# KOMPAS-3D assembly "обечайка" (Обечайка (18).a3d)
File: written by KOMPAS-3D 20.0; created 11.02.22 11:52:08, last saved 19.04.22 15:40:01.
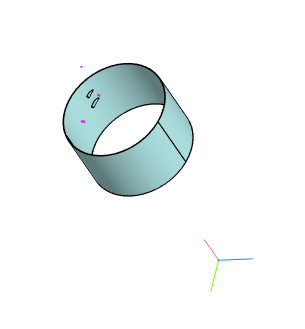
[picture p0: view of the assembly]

Document properties: Автор: Пользователь; Полное имя файла: D:\Загрузки\Обечайка (18).a3d

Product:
- Part/product: обечайка
    Масса: 4805.28
  - Component [detail]: обечайка  | Масса: 2381.45; Форматы листов документа: A4; additional columns: 2000; source file: >Деталь (локальная) 1.m3d, O:\КБ\Назаренко Олеся\От Зиновьева Дмитрия\Сладковско-заречное 1394П-УПН-4-ТХ.ТЗ\ТП 36-1000.016.03.100 - Ёмкость\ТП 36-1000.016.03.110 - Корпус емкости\ТП 36-1000.016.03.111 - Обечайка S16 L2000.cdw

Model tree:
1. Операция без истории:1
2. Поверхность без истории:1
3. Операция без истории:2
4. Операция без истории:3
5. Смещенная плоскость:1
     Расстояние = 6990
6. Эскиз:6
7. Эскиз:7
8. Эскиз:10
9. Эскиз:11
10. Смещенная плоскость:2  (with: Операция без истории:1)
     Расстояние = 10
11. Эскиз:12
12. Средняя плоскость:1
13. Смещенная плоскость:3
     Расстояние = 422
14. Эскиз:13
15. Плоскость под углом:1  (with: Эскиз:13)
     Угол = 120
16. Эскиз:14
17. Эскиз:15

Referenced files: >Деталь (локальная) 1.m3d
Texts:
  Точка начала. Х
  Точка начала. Y
  Точка начала. Z
  Основная 1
